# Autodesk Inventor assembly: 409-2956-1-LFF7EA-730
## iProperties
Created: 2010-06
Part Number: 409-2956-1-LFF7EA-730
Document SubType Name: Weldment
Designer: S. Boerckel
Mass: 6188.71 g
Surface Area: 2411.56 cm^2
Volume: 784.188 cm^3
Density: 7.89187 g/cm^3
Description: RH - PUMP DISCHARGE SPOOL
Weld Material: Welded Steel Mild
Material: ASSEMBLY
Author: S. Boerckel
Revision Number: B
Subject: DEMIN WATER FORWARDING PUMP SKID-7EA
